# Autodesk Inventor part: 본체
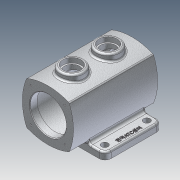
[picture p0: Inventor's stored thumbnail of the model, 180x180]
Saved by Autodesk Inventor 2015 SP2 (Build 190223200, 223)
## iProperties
Created: 2013-02
Part Number: 본체
Document SubType Name: Modeling
Designer: 한국산업디자인학원[gmhk.co.kr]
Density: 1 g/cm^3
Material: 일반
Appearance: _시험_알루미늄 표면거칠기
Author: 한국산업디자인학원[gmhk.co.kr]
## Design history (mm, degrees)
sketch "스케치1"
  geometry: L1 (-65, 55)-(65, 55); L2 (65, 55)-(65, -40); L3 (65, -40)-(-65, -40); L4 (-65, -40)-(-65, 55); 2 further points
  constraints: 8 end point, 2 parallel, 1 horizontal, 1 midpoint, 1 perpendicular, 1 vertical alignment
  dimensions: "d0" = 130 distance of L2.end L3.end; "d1" = 95 distance of L1.end L2.end; "d47" = 40 distance from line of L3 point (0, 0)
extrude "돌출1" new body sketch "스케치1" distance "d2" = 12; taper "d3" = 0 deg
sketch "스케치2"
  geometry: L1 (-35.355, 85.355)-(35.355, 85.355); L2 (35.355, 85.355)-(35.355, 14.645); L3 (35.355, 14.645)-(-35.355, 14.645); L4 (-35.355, 14.645)-(-35.355, 85.355); L5 (35.355, 85.355)-(-35.355, 14.645); L6 (65, 0)-(-65, 0) reference; A1 r 91.05 centre (0, 1.45) between (35.355, 85.355) and (-35.355, 85.355); A2 r 91.05 centre (-48.55, 50) between (35.355, 14.645) and (35.355, 85.355); A3 r 91.05 centre (0, 98.55) between (-35.355, 14.645) and (35.355, 14.645); A4 r 91.05 centre (48.55, 50) between (-35.355, 85.355) and (-35.355, 14.645); 3 further points
  constraints: 10 end point, 8 point on circle, 4 centre point, 3 equal radius, 2 midpoint, 2 parallel, 2 perpendicular, 1 horizontal, 1 vertical alignment
  dimensions: "d4" = 50 distance from line of point (0, 50) L6; "d5" = 50 distance of L1.start point (0, 50); "d6" = 85 dimension on A2 A4
extrude "돌출2" join sketch "스케치2" stored distance "d7" = 140; taper "d8" = 0 deg
sketch "스케치3"
  geometry: L1 (28.27, 12)-(65, 12) reference; L2 (-65, 12)-(-28.27, 12) reference; A1 r 91.05 centre (0, 98.55) between (-35.355, 14.645) and (35.355, 14.645) reference; A2 r 91.05 centre (48.55, 50) between (-35.355, 85.355) and (-35.355, 14.645) reference; A3 r 91.05 centre (-48.55, 50) between (35.355, 14.645) and (35.355, 85.355) reference; A4 r 5 centre (-41.653, 17) between (-41.653, 12) and (-36.957, 18.718); A5 r 5 centre (41.653, 17) between (36.957, 18.718) and (41.653, 12); 1 further point
  constraints: 6 point on circle, 4 tangent, 2 centre point, 2 point on line, 1 equal radius
  dimensions: "d9" = 5 radius of A5
extrude "돌출3" join sketch "스케치3" stored distance "d10" = 120; taper "d11" = 0 deg
fillet "모깎기1" dims "d12" = 3
fillet "모깎기2" dims "d13" = 10
fillet "모깎기3" dims "d14" = 3
sketch "스케치4"
  geometry: L1 (-70, 84.185)-(-70, 85.839) reference; L2 (-70, 15.815)-(-70, 84.185) reference; L3 (-70, 14.161)-(-70, 15.815) reference; L4 (-70, 14.161)-(-70, 14.161) reference; L5 (-70, 15.815)-(-70, 14.161) reference; L6 (-70, 84.185)-(-70, 15.815) reference; L7 (-70, 85.839)-(-70, 84.185) reference; L8 (-70, 85.839)-(-70, 85.839) reference; L9 (70, 15.815)-(70, 14.161) reference; L10 (70, 84.185)-(70, 15.815) reference; L11 (70, 85.839)-(70, 84.185) reference; L12 (70, 85.839)-(70, 85.839) reference; L13 (70, 84.185)-(70, 85.839) reference; L14 (70, 15.815)-(70, 84.185) reference; L15 (70, 14.161)-(70, 15.815) reference; L16 (70, 14.161)-(70, 14.161) reference; L17 (-70, 50)-(70, 50); L18 (-70, 80)-(-58, 80); L19 (-58, 80)-(-58, 87.5); L20 (-58, 87.5)-(58, 87.5); L21 (58, 87.5)-(58, 80); L22 (58, 80)-(70, 80); 1 further point
  constraints: 12 end point, 2 collinear, 2 midpoint, 2 parallel, 2 perpendicular, 2 point on line
  dimensions: "d15" = 60 diameter of L18 L17; "d16" = 75 diameter of L20 L17; "d17" = 12 distance of L18.start L18.end; "d18" = 12 distance of L21.end L22.end
revolve "회전1" sketch "스케치4" stored, may be unused: angle "d19" = 90 deg
fillet "모깎기4" dims "d20" = 3
node "작업 평면2"
  node "작업 평면1"
sketch "스케치5"
  geometry: C1 r 20 at (0, 30); C2 r 20 at (0, -30); 1 further point
  constraints: 2 centre point, 2 vertical alignment
  dimensions: "d22" = 40 diameter of C1; "d23" = 40 diameter of C2; "d24" = 60 distance of C2.centre C1.centre; "d25" = 30 distance of point (0, 0) C1.centre (= 0.5 x d24)
extrude "돌출4" join sketch "스케치5" stored distance "d26" = 120; taper "d27" = 0 deg
fillet "모깎기5" dims "d28" = 3
hole "구멍1" diameter "d31" = 25; stored, may be unused: countersink angle "d35" = 90 deg, drill point angle "d37" = 118 deg; dims "d29" = 10, "d30" = 10, "d32" = 6, "d33" = 30, "d34" = 8, "d36" = 8
hole "구멍2" diameter "d40" = 25; stored, may be unused: countersink angle "d44" = 90 deg, drill point angle "d46" = 118 deg; dims "d38" = 10, "d39" = 10, "d41" = 6, "d42" = 30, "d43" = 8, "d45" = 8
sketch "스케치6"
  geometry: L1 (65, -30)-(65, 45) reference; 4 further points
  constraints: 1 midpoint, 1 vertical alignment
  dimensions: "d48" = 13 distance from line of point (52, 42.5) L1; "d49" = 70 distance of point (52, -27.5) point (52, 42.5); "d50" = 35 vertical distance of point (65, 7.5) point (52, 42.5) (= 0.5 x d49)
hole "구멍3" sketch "스케치6" at (52, -27.5), (52, 42.5) diameter "d51" = 11; stored, may be unused: countersink angle "d55" = 90 deg, drill point angle "d57" = 118 deg; dims "d52" = 6, "d53" = 30, "d54" = 8, "d56" = 8
sketch "스케치8"
  geometry: L1 (65, -30)-(65, 45) reference; 3 further points
  constraints: 1 horizontal alignment, 1 midpoint, 1 other
  dimensions: "d60" = 8 distance from line of point (57, 7.5) L1
feature "엠보싱2" sketch "스케치8" dims "d0" = 130, "d1" = 95, "d47" = 40, "d61" = 1, "d62" = 0
chamfer "모따기1" distance "d63" = 1; stored, may be unused: second distance "d64" = 2, angle "d65" = 45 deg
sketch "스케치9" dims "d9" = 5
  geometry: L1 (0, 81)-(0, 50); L2 (0, 50)-(28.284, 78.284); 1 further point
  constraints: 4 end point, 1 vertical, 1 vertical alignment, 1 other
  dimensions: "d66" = 45 deg angle of L2 L1; "d67" = 40 distance of L2.end L1.end
hole "구멍4" sketch "스케치9" at (28.284, 78.284) diameter "d68" = 3.242; stored, may be unused: countersink angle "d72" = 90 deg, drill point angle "d74" = 118 deg; dims "d69" = 8, "d70" = 30, "d71" = 8, "d73" = 10
node "솔리드1"
mirror "대칭1"
pattern_circular "원형 패턴1" dims angle "d76" = 360 deg
mirror "대칭2"
node "투영된 루프1"
node "투영된 루프2"
